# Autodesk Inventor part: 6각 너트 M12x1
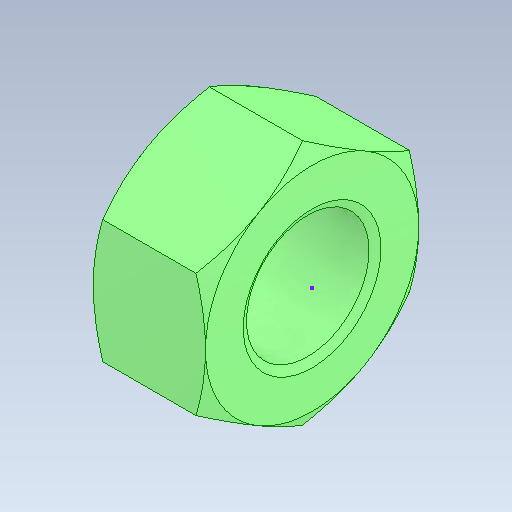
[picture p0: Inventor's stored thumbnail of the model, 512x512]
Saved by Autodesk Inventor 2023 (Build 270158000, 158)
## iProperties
Created: 2025-04
Part Number: 6각 너트 M12x1
Material: 강철, 연강
Description: 6각 너트
Document SubType Name: Modeling
Designer: Admin
Density: 7.85 g/cm^3
Appearance: 기본값
Author: jhkim
Sending System: Autodesk Inventor 2026
Preprocessor: ST-DEVELOPER v20.1
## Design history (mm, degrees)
node "복구된 형상1"
  node "스케치1"
feature "Solid1"
node "스케치3"
node "솔리드1"
